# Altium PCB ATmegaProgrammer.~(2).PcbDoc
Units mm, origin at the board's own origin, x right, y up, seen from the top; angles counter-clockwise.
Board outline 152.4 x 101.6 mm, 2 copper layers (Top Layer, Bottom Layer); 6 components, 8 nets, 42 pads, 4 vias.
Unrouted connection lines stored in the file: 16.
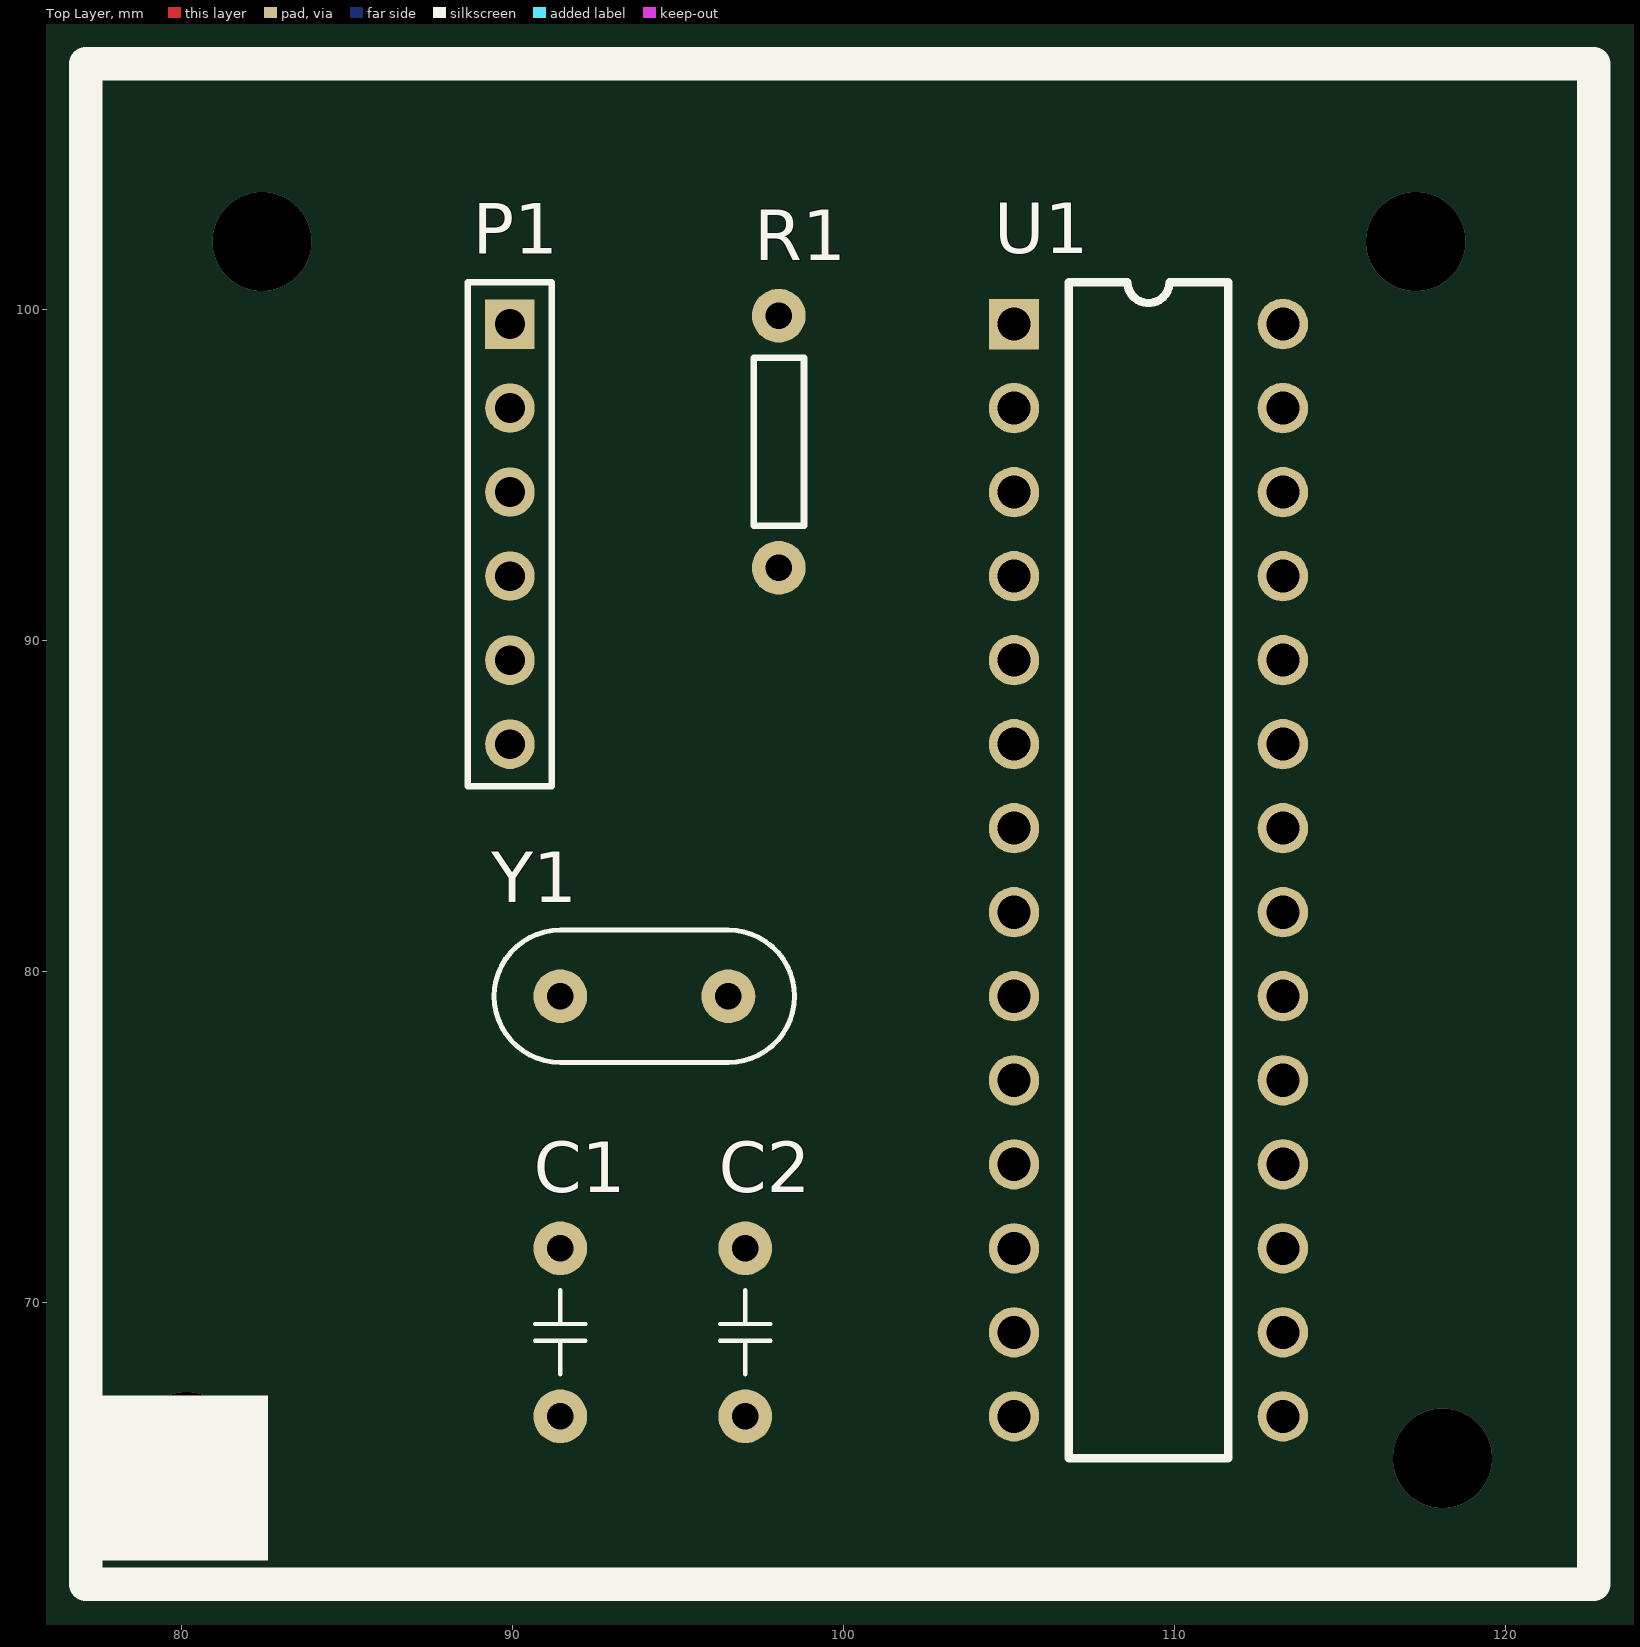
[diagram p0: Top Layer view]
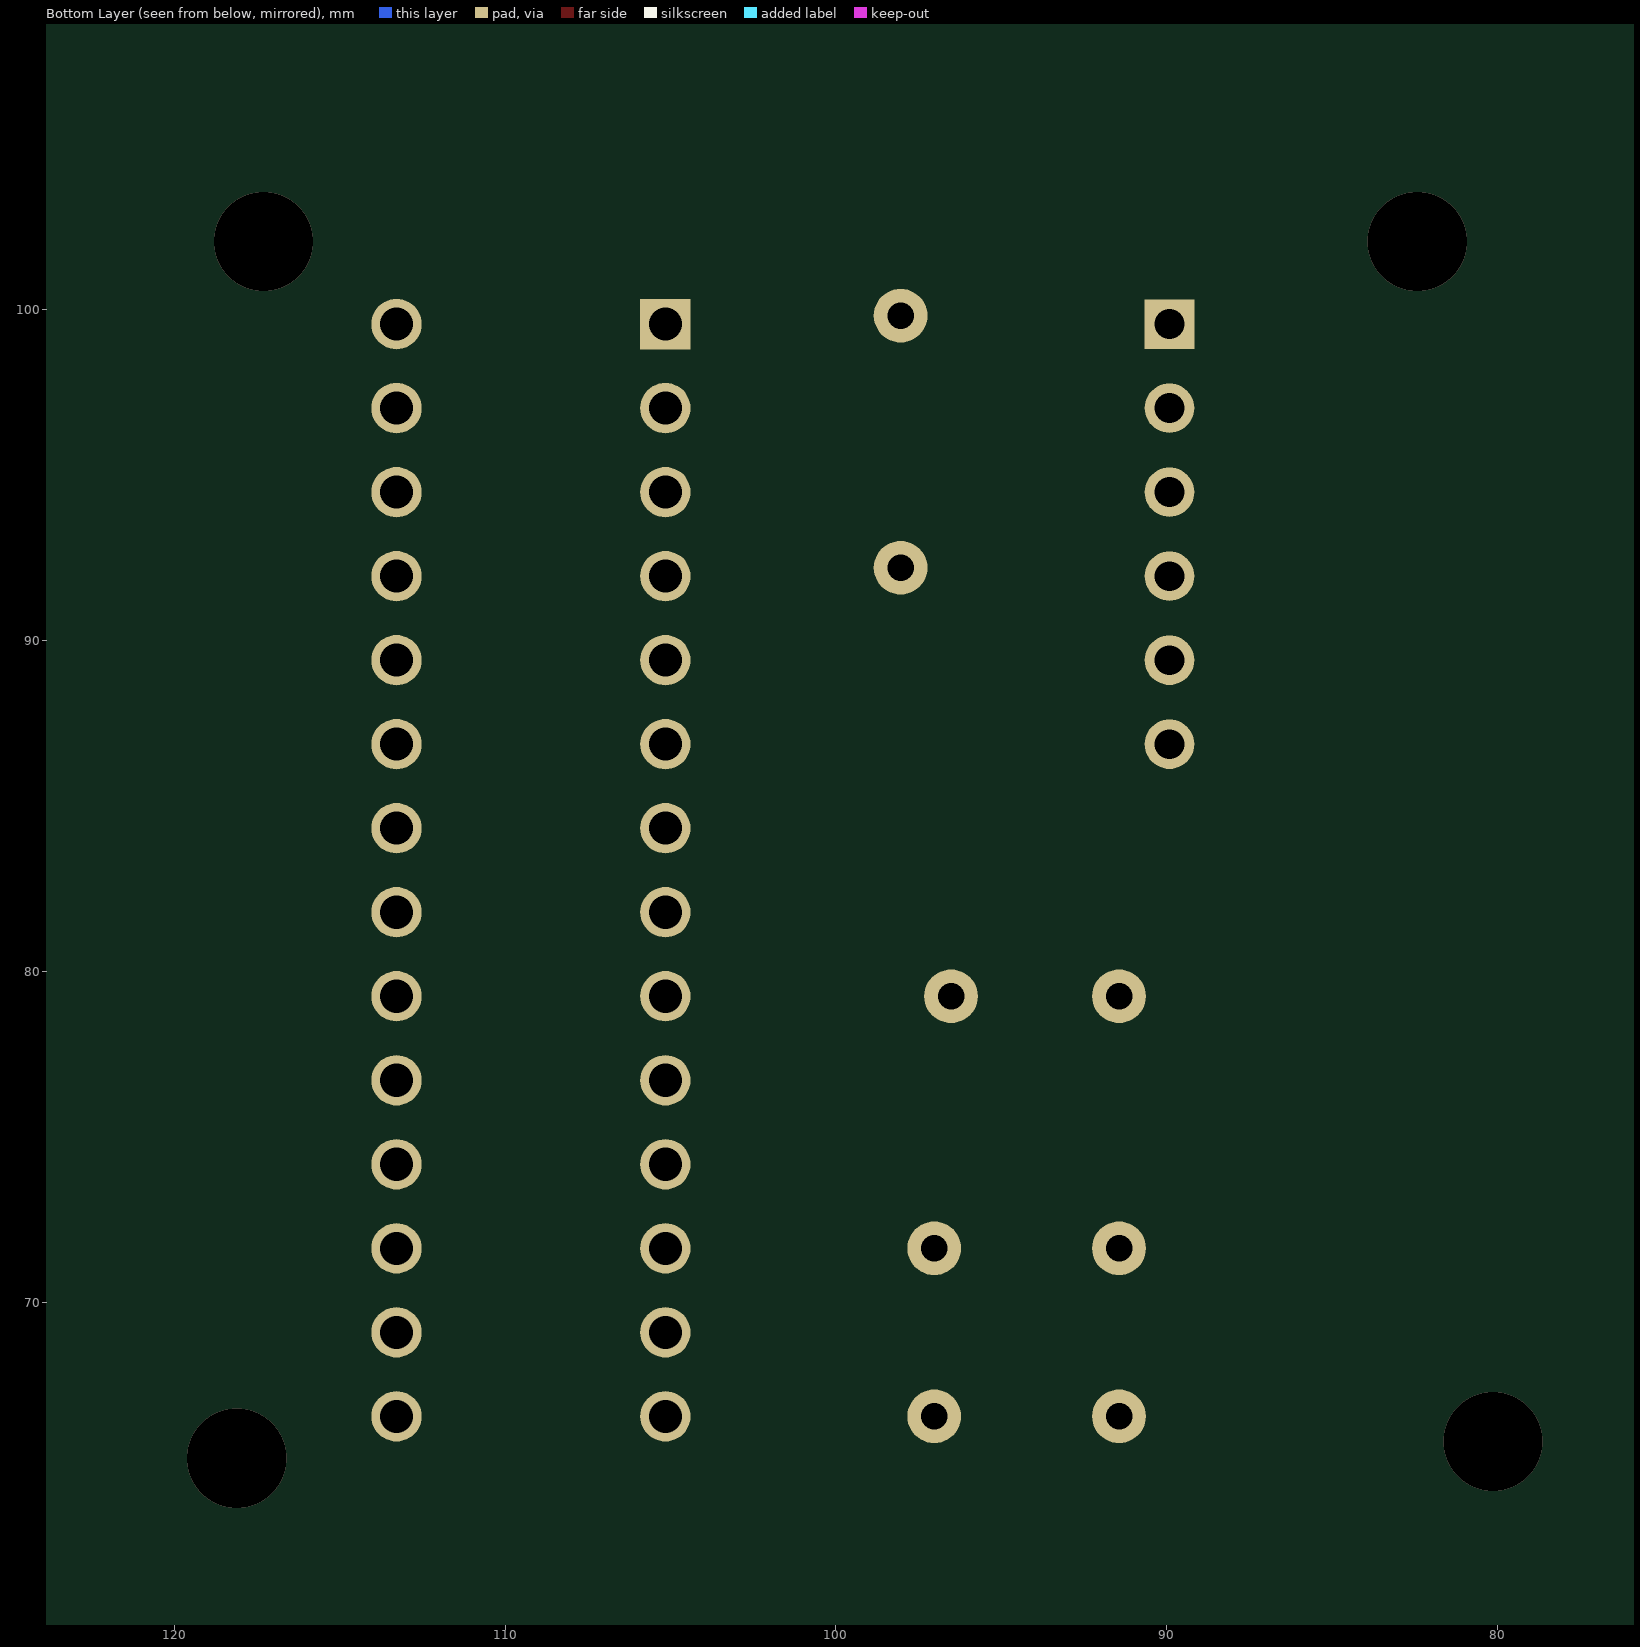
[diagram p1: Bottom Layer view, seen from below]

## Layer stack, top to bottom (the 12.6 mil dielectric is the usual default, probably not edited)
Top Layer: signal copper 0.0356
Dielectric: dielectric 0.32, FR-4, Dk 4.8
Bottom Layer: signal copper 0.0356

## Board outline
25.4,25.4 177.8,25.4 177.8,127 25.4,127

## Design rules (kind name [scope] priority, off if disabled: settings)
Clearance [All] p1: gap=0.254
PolygonConnect [All] p1: connectstyle=Relief reliefconductorwidth=0.254 reliefentries=4 polygonreliefangle="90 Angle"
RoutingVias [All] p1: holewidth=0.711 width=1.27 viastyle="Through Hole" minholewidth=0.711 minwidth=1.27 maxholewidth=0.711 maxwidth=1.27
SilkscreenOverComponentPads [All] p1: minsilkscreentomaskgap=0.254
SolderMaskExpansion [All] p1: expansion=0.102
Width [All] p1: maxlimit=0.254 minlimit=0.254 preferedwidth=0.254
27 further rules are at their usual default settings.

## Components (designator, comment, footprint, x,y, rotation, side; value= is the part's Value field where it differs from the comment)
C1 "Cap" C200 91.44,69.088 r0 top
C2 "Cap" C200 97.028,69.088 r0 top
P1 "Header 6" HDR1X6 89.916,99.568 r270 top
R1 "Res" AXIAL-0.3 98.044,96.012 r270 top
U1 "ATmega328" DIP28 105.156,99.568 r0 top
Y1 "16MHz" XTAL4-8 93.98,79.248 r180 top

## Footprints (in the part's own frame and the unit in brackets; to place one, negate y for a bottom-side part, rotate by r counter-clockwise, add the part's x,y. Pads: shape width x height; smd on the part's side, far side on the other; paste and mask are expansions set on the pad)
AXIAL-0.3 [mil] "0.3\" Resistor; 2 Leads"
  round 64 hole 31.5: 1(-150,0) 2(150,0)
  silkscreen extent -100,-30 100,30, body extent -161,-39 165,39, height 86
C200 [mil] "鹅溅筿甧竟"
  round 64 hole 31.5: 1(0,100) 2(0,-100)
  silkscreen extent -30,-50 30,50, body extent -41,-136 39,135, height 354
DIP28 [mil]
  rect 60x60 hole 39.37: 1(0,0)
  round 60 hole 39.37: 2(0,-100) 3(0,-200) 4(0,-300) 5(0,-400) 6(0,-500) 7(0,-600) 8(0,-700) 9(0,-800) 10(0,-900) 11(0,-1000) 12(0,-1100) 13(0,-1200) 14(0,-1300) 15(320,-1300) 16(320,-1200) 17(320,-1100) 18(320,-1000) 19(320,-900) 20(320,-800) 21(320,-700) 22(320,-600) 23(320,-500) 24(320,-400) 25(320,-300) 26(320,-200) 27(320,-100) 28(320,0)
  silkscreen extent 65,-1350 255,50, body extent 65,-1350 255,50, height 130
HDR1X6 [mm] "Connector; Header; 6 Position"
  rect 1.5x1.5 hole 0.9: 1(0,0)
  round 1.5 hole 0.9: 2(2.54,0) 3(5.08,0) 4(7.62,0) 5(10.16,0) 6(12.7,0)
  silkscreen extent -1.27,-1.27 13.97,1.27
XTAL4-8 [mil]
  round 64 hole 31.5: 1(-100,0) 2(100,0)
  silkscreen extent -179,-79 179,79, body extent -178,-80 192,79, height 157

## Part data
C1 C2: "Capacitor"
P1: "Header, 6-Pin"
R1: "Resistor"
U1: "ATmega¨t¦C³æ´¹¤ù"
Y1: library part XTAL, "Crystal Oscillator"

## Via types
v1: diameter 3, hole 3, Top Layer to Bottom Layer, 4 vias

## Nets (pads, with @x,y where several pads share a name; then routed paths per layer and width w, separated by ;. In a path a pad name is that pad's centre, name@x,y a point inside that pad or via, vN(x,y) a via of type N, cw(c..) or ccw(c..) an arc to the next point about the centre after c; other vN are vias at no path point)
GND: C1.1 C2.1 P1.6 U1.8 U1.22
MISO: P1.3 U1.18
MOSI: P1.2 U1.17
NetC1_2: C1.2 U1.10 Y1.2
NetC2_2: C2.2 U1.9 Y1.1
RESET: P1.1 R1.1 U1.1
SCK: P1.4 U1.19
VCC: P1.5 R1.2 U1.7 U1.20
pads on no net: U1.2 U1.3 U1.4 U1.5 U1.6 U1.11 U1.12 U1.13 U1.14 U1.15 U1.16 U1.21 U1.23 U1.24 U1.25 U1.26 U1.27 U1.28
copper on no net:
  other v1: 118.11,65.278 80.137,65.786 82.423,102.061 117.301,102.061

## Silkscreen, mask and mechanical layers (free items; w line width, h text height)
Top Overlay:
  rectangle: 77.597,62.183 82.597,67.183
  lines w1.016: 77.343,61.468 77.089,61.468 ; 77.089,61.468 77.089,107.442 122.682,107.442 122.682,61.468 77.089,61.468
